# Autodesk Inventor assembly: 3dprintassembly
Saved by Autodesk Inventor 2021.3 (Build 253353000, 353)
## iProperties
Created: 2022-04
Part Number: 3dprintassembly
Document SubType Name: Assembly
Designer: Administrator
Title: 3dprintassembly v2
Author: Administrator
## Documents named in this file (3)
- c:\worker\convert-fusion-r02\tmp\job-1\1494\output\files\edf93e89-3626-4d1b-8d7b-242b6fcac1eb\d101c159-3fc4-4491-a5f4-d3ff12334e3e.iam
- c:\worker\convert-fusion-r02\tmp\job-1\1494\output\files\edf93e89-3626-4d1b-8d7b-242b6fcac1eb\4931T333_Bracket Fastener Set for 1-1 2 Square Rail Bolt-Together Framing v1.ipt
- c:\worker\convert-fusion-r02\tmp\job-1\1494\output\files\edf93e89-3626-4d1b-8d7b-242b6fcac1eb\LongSteelTubingAssembled v6.ipt
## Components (3 placed, 2 different names)
1. 4931T333_Bracket Fastener Set for 1-1 2 Square Rail Bolt-Together Framing v1:1
2. LongSteelTubingAssembled v6:1
3. 4931T333_Bracket Fastener Set for 1-1 2 Square Rail Bolt-Together Framing v1:2
